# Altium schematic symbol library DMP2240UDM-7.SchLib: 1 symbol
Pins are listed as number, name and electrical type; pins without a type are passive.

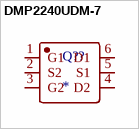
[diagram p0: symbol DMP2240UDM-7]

## DMP2240UDM-7
designator Q??
footprint SOT-26_L3.0-W1.6-P0.95-LS2.8-BL
pins: 1 G1, 2 S2, 3 G2, 4 D2, 5 S1, 6 D1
